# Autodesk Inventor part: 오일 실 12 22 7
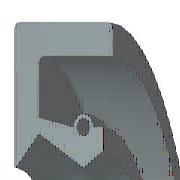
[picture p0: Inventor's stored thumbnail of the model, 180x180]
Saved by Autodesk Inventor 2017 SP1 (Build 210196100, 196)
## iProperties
IsCustomPart: 1
Created: 2012-02
Part Number: 오일 실 12 22 7
Material: 고무
Description: 오일-실
Document SubType Name: Modeling
Standard: KS B 2804
Designer: mduedu
Standards Organization: KS
Language: ko-KR
Size Designation: D - 12 22 7
Categories: <MemberInstance><Categories><Category DisplayName="샤프트 부품" InternalName="7f7aeb1f-a693-4053-b835-cee3144e0d98" Mnemonic="SHFT"><Category DisplayName="실링" Intern
Density: 0.93 g/cm^3
Mass: 1.25383 g
Surface Area: 18.4996 cm^2
Volume: 1.3482 cm^3
Appearance: 고무 - 검은색 - 버전 1.1
Author: mduedu
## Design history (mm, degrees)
revolve "본체" stored, may be unused: angle "d17" = 90 deg
revolve "스프링1" stored, may be unused: angle "d18" = 90 deg
body "Solid1"
sketch "스케치1"
  geometry: L1 (0, 11)-(7, 11); L2 (7, 9.25)-(1.75, 9.25); L3 (1.75, 7.75)-(4.9, 6); L4 (4.9, 6)-(0, 6); L5 (0, 0)-(9.586, 0) reference; L6 (4.9, 6)-(6.3, 6.875); L7 (0, 18)-(0, -3) reference; L8 (-1.941, 0)-(11.507, 0) reference; L9 (4.2, 8.1)-(1.75, 8.59); L10 (1.75, 8.59)-(1.75, 9.25); L11 (0, 11)-(0, 6.088); L12 (4.9, 6)-(0, 6); L13 (1.75, 7.75)-(0.152, 6.028); L14 (7, 11)-(7, 9.25); L15 (5.6, 8.1)-(6.3, 8.1); L16 (6.3, 8.1)-(6.3, 6.875); C1 r 0.455 at (4.9, 8.1); A1 r 0.7 centre (4.9, 8.1) between (5.6, 8.1) and (4.2, 8.1); A2 r 0.088 centre (0.088, 6.088) between (0, 6.088) and (0.152, 6.028); 1 further point
  constraints: 28 end point, 5 horizontal alignment, 5 point on line, 4 point on circle, 4 vertical alignment, 3 centre point, 3 tangent, 2 collinear, 2 horizontal, 2 perpendicular, 1 coincident, 1 parallel
  dimensions: "d0" = 22 diameter of L1 L5 (= SD2); "d1" = 1.75 distance of L1.end L2.start (= SD); "d2" = 0.91 diameter of C1 (= SPDI); "d3" = 1.4 diameter of A1 (= SPDA); "d4" = 12 diameter of L3.end L5 (= NND); "d5" = 15.5 diameter of L3.start L5 (= TKDM); "d7" = 17.18 diameter of L9.end L5 (= TKDM + 0.24 x SWDT); "d8" = 1.75 distance between parallel lines of L11 L10 (= SD); "d9" = 4.9 distance from line of L11 C1.centre (= SPDST); "d10" = 16.2 diameter of C1.centre L5 (= HLDM); "d11" = 0.0875 radius of A2 (= 0.25 x LAB); "d12" = 6.3 distance between parallel lines of L11 L16 (= SDI); "d13" = 13.75 diameter of L6.end L5 (= ABDM); "d14" = 7 distance from line of L11 L1.end (= SWDT)
fillet "모깎기1" dims "d6" = 0.3 (= RR)
other parameters: "SD2" = 22 [user parameter; used in 1 equation term], "SWDT" = 7 [user parameter; used in 2 equation terms], "RR" = 0.3 [user parameter; used in 1 equation term], "SD" = 1.75 [user parameter; used in 2 equation terms], "NND" = 12 [user parameter; used in 1 equation term], "SPDA" = 1.4 [user parameter; used in 1 equation term], "SPDI" = 0.91 [user parameter; used in 1 equation term], "TKDM" = 15.5 [user parameter; used in 2 equation terms], "HLDM" = 16.2 [user parameter; used in 1 equation term], "ABDM" = 13.75 [user parameter; used in 1 equation term], "SDI" = 6.3 [user parameter; used in 1 equation term], "SPDST" = 4.9 [user parameter; used in 1 equation term], "LAB" = 0.35 [user parameter; used in 1 equation term], "d15" = 0, "d16" = 0, "d19" = 0
